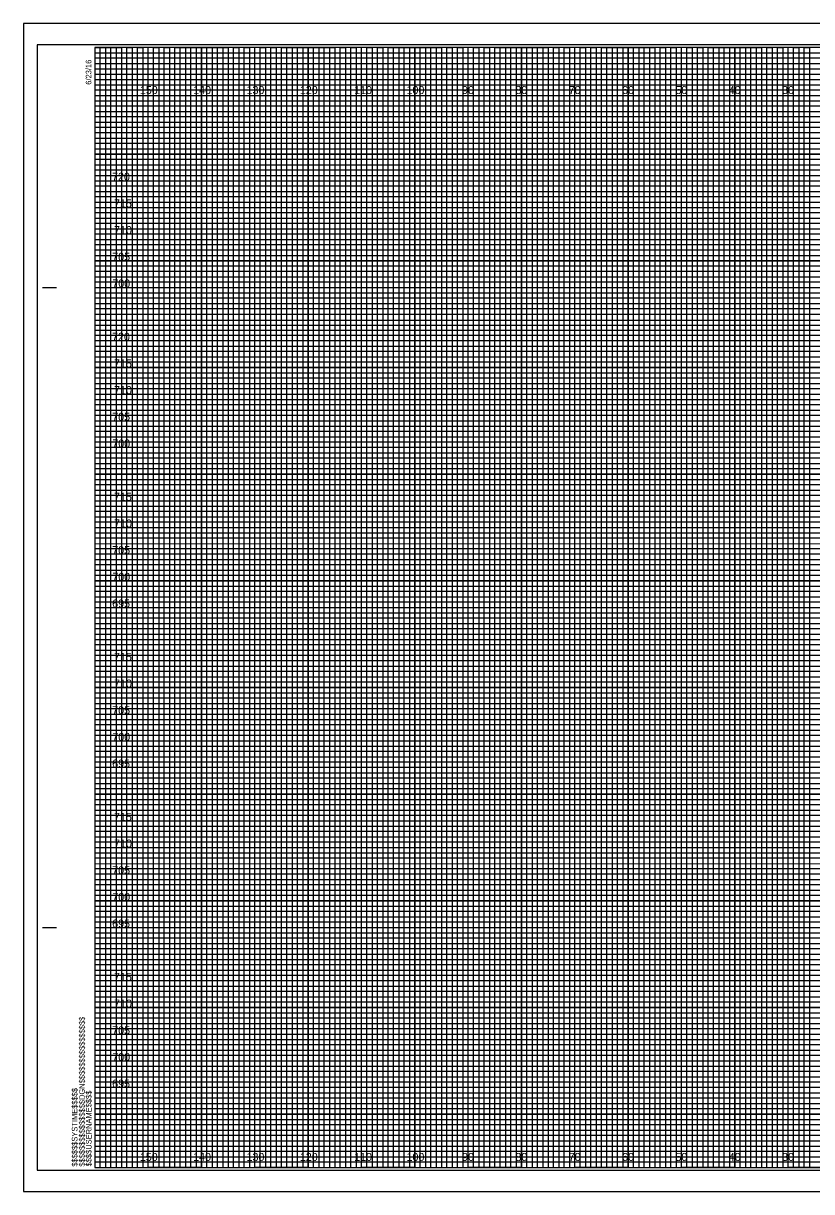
# Model space of a CAD drawing. Extents: x -13 to 323, y -5 to 434.
# Drawn here: x -13.4 to 134.4, y -4.5 to 214.5 of the extents above; entities that cross this region are included whole.
import ezdxf

# ---------------------------------------------------------------- set-up
doc = ezdxf.new("R2010")
doc.units = 0
for name, color, linetype in [('Exist CMT Pavement', 7, 'Continuous'), ('Exist Cross Section Cell', 7, 'Continuous'), ('Exist XS Center Line Elevation Label', 7, 'Continuous'), ('Exist XS Ground Line', 7, 'Continuous'), ('Prop CMT Pvmt Course 1 Wedge', 7, 'Continuous'), ('Prop CMT Pvmt Course 2', 7, 'Continuous'), ('Prop CMT Pvmt Course 3', 7, 'Continuous'), ('Prop CMT Shld Paved Course 1', 7, 'Continuous'), ('Prop CMT Shld Paved Course 2', 7, 'Continuous'), ('Prop CMT Subgrade Earthwork', 7, 'Continuous'), ('Scratch_Level_1', 7, 'Continuous')]:
    doc.layers.add(name, color=color, linetype=linetype)

msp = doc.modelspace()

# ---------------------------------------------------------------- linework, layer by layer
at = {"layer": 'Exist XS Center Line Elevation Label'}
for points in [[(0, 210), (5, 210), (5, 0), (15, 0), (15, 210), (25, 210), (25, 0), (35, 0), (35, 210), (45, 210), (45, 0), (55, 0), (55, 210), (65, 210), (65, 0), (75, 0), (75, 210), (85, 210), (85, 0), (95, 0), (95, 210), (105, 210), (105, 0), (115, 0), (115, 210), (125, 210), (125, 0), (135, 0)], [(0, 205), (275, 205)], [(0, 185), (320, 185), (320, 195), (0, 195)], [(0, 165), (320, 165), (320, 175), (0, 175)], [(0, 145), (320, 145), (320, 155), (0, 155)], [(0, 125), (320, 125), (320, 135), (0, 135)], [(0, 105), (320, 105), (320, 115), (0, 115)], [(0, 85), (320, 85), (320, 95), (0, 95)], [(0, 65), (320, 65), (320, 75), (0, 75)], [(0, 45), (320, 45), (320, 55), (0, 55)], [(0, 25), (320, 25), (320, 35), (0, 35)], [(0, 5), (320, 5), (320, 15), (0, 15)]]:
    msp.add_lwpolyline(points, dxfattribs=at)
at = {"layer": 'Exist XS Ground Line'}
for p, q in [((10, 210), (0, 210)), ((10, 0), (10, 210)), ((30, 210), (20, 210)), ((20, 210), (20, 0)), ((30, 0), (30, 210)), ((50, 210), (40, 210)), ((40, 210), (40, 0)), ((50, 0), (50, 210)), ((70, 210), (60, 210)), ((60, 210), (60, 0)), ((70, 0), (70, 210)), ((90, 210), (80, 210)), ((80, 210), (80, 0)), ((90, 0), (90, 210)), ((110, 210), (100, 210)), ((100, 210), (100, 0)), ((110, 0), (110, 210)), ((130, 210), (120, 210)), ((120, 210), (120, 0)), ((130, 0), (130, 210)), ((20, 0), (10, 0)), ((40, 0), (30, 0)), ((60, 0), (50, 0)), ((80, 0), (70, 0)), ((100, 0), (90, 0)), ((120, 0), (110, 0)), ((140, 0), (130, 0))]:
    msp.add_line(p, q, dxfattribs=at)
for points in [[(0, 200), (320, 200), (320, 190), (0, 190)], [(0, 180), (320, 180), (320, 170), (0, 170)], [(0, 160), (320, 160), (320, 150), (0, 150)], [(0, 140), (320, 140), (320, 130), (0, 130)], [(0, 120), (320, 120), (320, 110), (0, 110)], [(0, 100), (320, 100), (320, 90), (0, 90)], [(0, 80), (320, 80), (320, 70), (0, 70)], [(0, 60), (320, 60), (320, 50), (0, 50)], [(0, 40), (320, 40), (320, 30), (0, 30)], [(0, 20), (320, 20), (320, 10), (0, 10)]]:
    msp.add_lwpolyline(points, dxfattribs=at)
at = {"layer": 'Prop CMT Pvmt Course 1 Wedge'}
for p, q in [((323.3, 214.5), (-13.4, 214.5)), ((-13.4, 214.5), (-13.4, -4.5)), ((-13.4, -4.5), (323.3, -4.5))]:
    msp.add_line(p, q, dxfattribs=at)
at = {"layer": 'Prop CMT Pvmt Course 2'}
msp.add_lwpolyline([(-13.4, -4.5), (323.3, -4.5), (323.3, 214.5), (-13.4, 214.5)], close=True, dxfattribs=at)
at = {"layer": 'Prop CMT Pvmt Course 3'}
msp.add_lwpolyline([(-10.8, -0.5), (322.4, -0.5), (322.4, 210.5), (-10.8, 210.5)], close=True, dxfattribs=at)
at = {"layer": 'Prop CMT Shld Paved Course 1'}
for p, q in [((-9.8, 165), (-7.3, 165)), ((-9.7, 165), (-7.2, 165)), ((-9.8, 45), (-7.3, 45)), ((-9.7, 45), (-7.2, 45)), ((0, 0), (0, 0)), ((0, 0), (0, 0)), ((0, 0), (0, 0)), ((0, 0), (0, 0)), ((0, 0), (0, 0)), ((0, 0), (0, 0)), ((0, 0), (0, 0))]:
    msp.add_line(p, q, dxfattribs=at)
msp.add_lwpolyline([(320, 210), (0, 210), (0, 0), (320, 0)], close=True, dxfattribs=at)
at = {"layer": 'Prop CMT Shld Paved Course 2'}
for points in [[(0, 0), (1, 0), (1, 210), (2, 210), (2, 0)], [(2, 0), (3, 0), (3, 210), (4, 210), (4, 0)], [(5, 0), (6, 0), (6, 210), (7, 210), (7, 0)], [(7, 0), (8, 0), (8, 210), (9, 210), (9, 0)], [(10, 0), (11, 0), (11, 210), (12, 210), (12, 0)], [(12, 0), (13, 0), (13, 210), (14, 210), (14, 0)], [(15, 0), (16, 0), (16, 210), (17, 210), (17, 0)], [(17, 0), (18, 0), (18, 210), (19, 210), (19, 0)], [(20, 0), (21, 0), (21, 210), (22, 210), (22, 0)], [(22, 0), (23, 0), (23, 210), (24, 210), (24, 0)], [(25, 0), (26, 0), (26, 210), (27, 210), (27, 0)], [(27, 0), (28, 0), (28, 210), (29, 210), (29, 0)], [(30, 0), (31, 0), (31, 210), (32, 210), (32, 0)], [(32, 0), (33, 0), (33, 210), (34, 210), (34, 0)], [(35, 0), (36, 0), (36, 210), (37, 210), (37, 0)], [(37, 0), (38, 0), (38, 210), (39, 210), (39, 0)], [(40, 0), (41, 0), (41, 210), (42, 210), (42, 0)], [(42, 0), (43, 0), (43, 210), (44, 210), (44, 0)], [(45, 0), (46, 0), (46, 210), (47, 210), (47, 0)], [(47, 0), (48, 0), (48, 210), (49, 210), (49, 0)], [(50, 0), (51, 0), (51, 210), (52, 210), (52, 0)], [(52, 0), (53, 0), (53, 210), (54, 210), (54, 0)], [(55, 0), (56, 0), (56, 210), (57, 210), (57, 0)], [(57, 0), (58, 0), (58, 210), (59, 210), (59, 0)], [(60, 0), (61, 0), (61, 210), (62, 210), (62, 0)], [(62, 0), (63, 0), (63, 210), (64, 210), (64, 0)], [(65, 0), (66, 0), (66, 210), (67, 210), (67, 0)], [(67, 0), (68, 0), (68, 210), (69, 210), (69, 0)], [(70, 0), (71, 0), (71, 210), (72, 210), (72, 0)], [(72, 0), (73, 0), (73, 210), (74, 210), (74, 0)], [(75, 0), (76, 0), (76, 210), (77, 210), (77, 0)], [(77, 0), (78, 0), (78, 210), (79, 210), (79, 0)], [(80, 0), (81, 0), (81, 210), (82, 210), (82, 0)], [(82, 0), (83, 0), (83, 210), (84, 210), (84, 0)], [(85, 0), (86, 0), (86, 210), (87, 210), (87, 0)], [(87, 0), (88, 0), (88, 210), (89, 210), (89, 0)], [(90, 0), (91, 0), (91, 210), (92, 210), (92, 0)], [(92, 0), (93, 0), (93, 210), (94, 210), (94, 0)], [(95, 0), (96, 0), (96, 210), (97, 210), (97, 0)], [(97, 0), (98, 0), (98, 210), (99, 210), (99, 0)], [(100, 0), (101, 0), (101, 210), (102, 210), (102, 0)], [(102, 0), (103, 0), (103, 210), (104, 210), (104, 0)], [(105, 0), (106, 0), (106, 210), (107, 210), (107, 0)], [(107, 0), (108, 0), (108, 210), (109, 210), (109, 0)], [(110, 0), (111, 0), (111, 210), (112, 210), (112, 0)], [(112, 0), (113, 0), (113, 210), (114, 210), (114, 0)], [(115, 0), (116, 0), (116, 210), (117, 210), (117, 0)], [(117, 0), (118, 0), (118, 210), (119, 210), (119, 0)], [(120, 0), (121, 0), (121, 210), (122, 210), (122, 0)], [(122, 0), (123, 0), (123, 210), (124, 210), (124, 0)], [(125, 0), (126, 0), (126, 210), (127, 210), (127, 0)], [(127, 0), (128, 0), (128, 210), (129, 210), (129, 0)], [(130, 0), (131, 0), (131, 210), (132, 210), (132, 0)], [(132, 0), (133, 0), (133, 210), (134, 210), (134, 0)]]:
    msp.add_lwpolyline(points, dxfattribs=at)
at = {"layer": 'Prop CMT Subgrade Earthwork'}
for p, q in [((10, 0), (10, 210)), ((20, 0), (20, 210)), ((30, 0), (30, 210)), ((40, 0), (40, 210)), ((50, 0), (50, 210)), ((60, 0), (60, 210)), ((70, 0), (70, 210)), ((80, 0), (80, 210)), ((90, 0), (90, 210)), ((100, 0), (100, 210)), ((110, 0), (110, 210)), ((120, 0), (120, 210)), ((130, 0), (130, 210)), ((0, 200), (320, 200)), ((0, 190), (320, 190)), ((0, 180), (320, 180)), ((0, 170), (320, 170)), ((0, 160), (320, 160)), ((0, 150), (320, 150)), ((0, 140), (320, 140)), ((0, 130), (320, 130)), ((0, 120), (320, 120)), ((0, 110), (320, 110)), ((0, 100), (320, 100)), ((0, 90), (320, 90)), ((0, 80), (320, 80)), ((0, 70), (320, 70)), ((0, 60), (320, 60)), ((0, 50), (320, 50)), ((0, 40), (320, 40)), ((0, 30), (320, 30)), ((0, 20), (320, 20)), ((0, 10), (320, 10))]:
    msp.add_line(p, q, dxfattribs=at)
at = {"layer": 'Scratch_Level_1'}
for p, q in [((0, 209), (260, 209)), ((260, 207.98), (0, 207.98)), ((0, 207.98), (0, 207)), ((0, 207), (260, 207)), ((260, 205.89), (0, 205.89)), ((0, 205.89), (0, 204)), ((0, 204), (320, 204))]:
    msp.add_line(p, q, dxfattribs=at)
for points in [[(0, 203), (270, 203), (320, 203), (320, 202), (0, 202)], [(0, 201), (320, 201), (320, 199), (0, 199)], [(0, 198), (320, 198), (320, 197), (0, 196.98)], [(0, 196), (320, 196), (320, 194), (0, 194)], [(0, 193), (320, 193), (320, 192), (0, 192)], [(0, 191), (320, 191), (320, 189), (0, 189)], [(0, 188), (320, 188), (320, 187), (0, 187)], [(0, 186), (320, 186), (320, 184), (0, 184)], [(0, 183), (320, 183), (320, 182), (0, 182)], [(0, 181), (320, 181), (320, 179), (0, 179)], [(0, 178), (320, 178), (320, 177), (0, 177)], [(0, 176), (320, 176), (320, 173.95), (320, 173), (320, 172), (0, 172)], [(0, 174), (320, 174), (320, 173), (0, 173)], [(0, 171), (320, 171), (320, 169), (0, 169.03)], [(0, 169.03), (320, 169), (320, 168), (0, 168)], [(0, 167), (320, 167), (320, 166), (0, 166)], [(0, 164), (320, 164), (320, 163), (0, 163)], [(0, 162), (320, 162), (320, 161), (0, 161)], [(-0.07, 158.89), (320, 158.89), (320, 157.88), (-0.07, 157.88)], [(0, 157), (320, 157), (320, 156), (0, 156)], [(0, 154), (320, 154), (320, 153), (0, 153)], [(0, 152), (320, 152), (320, 151), (0, 151)], [(0, 149), (320, 149), (320, 148), (0, 148)], [(0, 147), (320, 147), (320, 146), (0, 146)], [(0, 144), (320, 144), (320, 143), (0, 143)], [(0, 142), (320, 142), (320, 141), (0, 141)], [(0, 139), (320, 139), (319.99, 137.98), (0, 138)], [(0, 137), (320, 137), (320, 136), (0, 136)], [(0, 134), (320, 134), (320, 133), (0, 133)], [(0, 132), (320, 132), (320, 131), (0, 131)], [(0, 129), (320, 129), (320, 128), (0, 128)], [(0, 127), (320, 127), (320, 126), (0, 126)], [(0, 124), (320, 124), (320, 123), (0, 123)], [(0, 122), (320, 122), (320, 121), (0, 121)], [(0, 119), (320, 119), (320, 118), (0, 118)], [(0, 116.99), (320.07, 116.91), (320, 116), (0, 116)], [(0, 114), (320, 114), (320, 113), (0, 113)], [(0, 112), (320, 112), (320, 111), (0, 111)], [(0, 109), (320, 109), (320, 108), (0, 108)], [(0, 107), (320, 107), (320, 106), (0, 106)], [(0, 104), (320, 104), (320, 103), (0, 103)], [(0, 102), (320, 102), (320, 101), (0, 101)], [(0, 99), (320, 99), (320, 98), (0, 98)], [(0, 97), (320, 97), (320, 96), (0, 96)], [(0, 94), (320, 94), (320, 93), (0, 93)], [(0, 92), (320, 92), (320, 91), (0, 91)], [(0, 89), (320, 89), (320, 88), (0, 88)], [(0, 87), (320, 87), (320, 86), (0, 86)], [(0, 84), (320, 84), (320, 83), (0, 83)], [(0, 82), (320, 82), (320, 81), (0, 81)], [(0, 79), (320, 79), (319.99, 77.98), (0, 78)], [(0, 77), (320, 77), (320, 76), (0, 76)], [(0, 74), (320, 74), (320, 73), (0, 73)], [(0, 72), (320, 72), (320, 71), (0, 71)], [(0, 69), (320, 69), (320, 68), (0, 68)], [(0, 67), (320, 67), (320, 66), (0, 66)], [(0, 64), (320, 64), (320, 63), (0, 63)], [(0, 62), (320, 62), (320, 61), (0, 61)], [(0, 59), (320, 59), (320, 58), (0, 58)], [(0, 56.99), (320.07, 56.91), (320, 56), (0, 56)], [(0, 54), (320, 54), (320, 53), (0, 53)], [(0, 52), (320, 52), (320, 51), (0, 51)], [(0, 49), (320, 49), (320, 48), (0, 48)], [(0, 47), (320, 47), (320, 46), (0, 46)], [(0, 44), (320, 44), (320, 43), (0, 43)], [(0, 42), (320, 42), (320, 41), (0, 41)], [(0, 39), (320, 39), (320, 38), (0, 38)], [(0, 37), (320, 37), (320, 36), (0, 36)], [(0, 34), (320, 34), (320, 33), (0, 33)], [(0, 32), (320, 32), (320, 31), (0, 31)], [(0, 29), (320, 29), (320, 28), (0, 28)], [(0, 27), (320, 27), (320, 26), (0, 26)], [(0, 24), (320, 24), (320, 23), (0, 23)], [(0, 22), (320, 22), (320, 21), (0, 21)], [(0, 19), (320, 19), (320, 18), (0, 18)], [(0, 17), (320, 17), (320, 16), (0, 16)], [(0, 14), (320, 14), (320, 13), (0, 13)], [(0, 12), (320, 12), (320, 11), (0, 11)], [(0, 9), (320, 9), (320, 8), (0, 8)], [(0, 7), (320, 7), (320, 6), (0, 6)], [(0, 4), (320, 4), (320, 3), (0, 3)], [(0, 2), (320, 2), (320, 1), (0, 1)]]:
    msp.add_lwpolyline(points, dxfattribs=at)

# ---------------------------------------------------------------- texts
at = {"layer": 'Exist CMT Pavement'}
for s, p in [('720', (3.23, 185)), ('715', (3.59, 180)), ('710', (3.61, 175)), ('705', (3.26, 170)), ('700', (3.28, 165)), ('720', (3.23, 155)), ('715', (3.59, 150)), ('710', (3.61, 145)), ('705', (3.26, 140)), ('700', (3.28, 135)), ('715', (3.59, 125)), ('710', (3.61, 120)), ('705', (3.26, 115)), ('700', (3.28, 110)), ('695', (3.25, 105)), ('715', (3.59, 95)), ('710', (3.61, 90)), ('705', (3.26, 85)), ('700', (3.28, 80)), ('695', (3.25, 75)), ('715', (3.59, 65)), ('710', (3.61, 60)), ('705', (3.26, 55)), ('700', (3.28, 50)), ('695', (3.25, 45)), ('715', (3.59, 35)), ('710', (3.61, 30)), ('705', (3.26, 25)), ('700', (3.28, 20)), ('695', (3.25, 15))]:
    msp.add_text(s, height=1.5, dxfattribs=at).set_placement(p)
at = {"layer": 'Exist Cross Section Cell'}
for s, p in [('150', (8.44, 201.25)), ('140', (18.44, 201.25)), ('130', (28.44, 201.25)), ('120', (38.44, 201.25)), ('110', (48.62, 201.25)), ('100', (58.44, 201.25)), ('90', (68.86, 201.25)), ('80', (78.86, 201.25)), ('70', (88.86, 201.25)), ('60', (98.86, 201.25)), ('50', (108.86, 201.25)), ('40', (118.86, 201.25)), ('30', (128.86, 201.25)), ('150', (8.44, 1.25)), ('140', (18.44, 1.25)), ('130', (28.44, 1.25)), ('120', (38.44, 1.25)), ('110', (48.62, 1.25)), ('100', (58.44, 1.25)), ('90', (68.86, 1.25)), ('80', (78.86, 1.25)), ('70', (88.86, 1.25)), ('60', (98.86, 1.25)), ('50', (108.86, 1.25)), ('40', (118.86, 1.25)), ('30', (128.86, 1.25))]:
    msp.add_text(s, height=1.5, dxfattribs=at).set_placement(p)
at = {"layer": 'Prop CMT Shld Paved Course 1'}
for s, p in [('6/23/16', (-0.65, 203)), ('$$$$$$$$$$$$$$$$DGN$$$$$$$$$$$$$$$$', (-1.88, 0.18)), ('$$$$$$SYSTIME$$$$$', (-3.26, 0.18)), ('$$$$USERNAME$$$$', (-0.62, 0.23))]:
    msp.add_text(s, height=1.05, rotation=90, dxfattribs=at).set_placement(p)

doc.saveas('drawing.dxf')
